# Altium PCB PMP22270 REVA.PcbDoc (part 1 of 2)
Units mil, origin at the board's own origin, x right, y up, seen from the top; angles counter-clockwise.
Board outline 4330.71 x 3937.01 mil, 4 copper layers (Top Layer, Signal Layer 1, Signal Layer 2, Bottom Layer), stack 41.2 mil thick; 92 components, 40 nets, 216 pads, 127 vias.
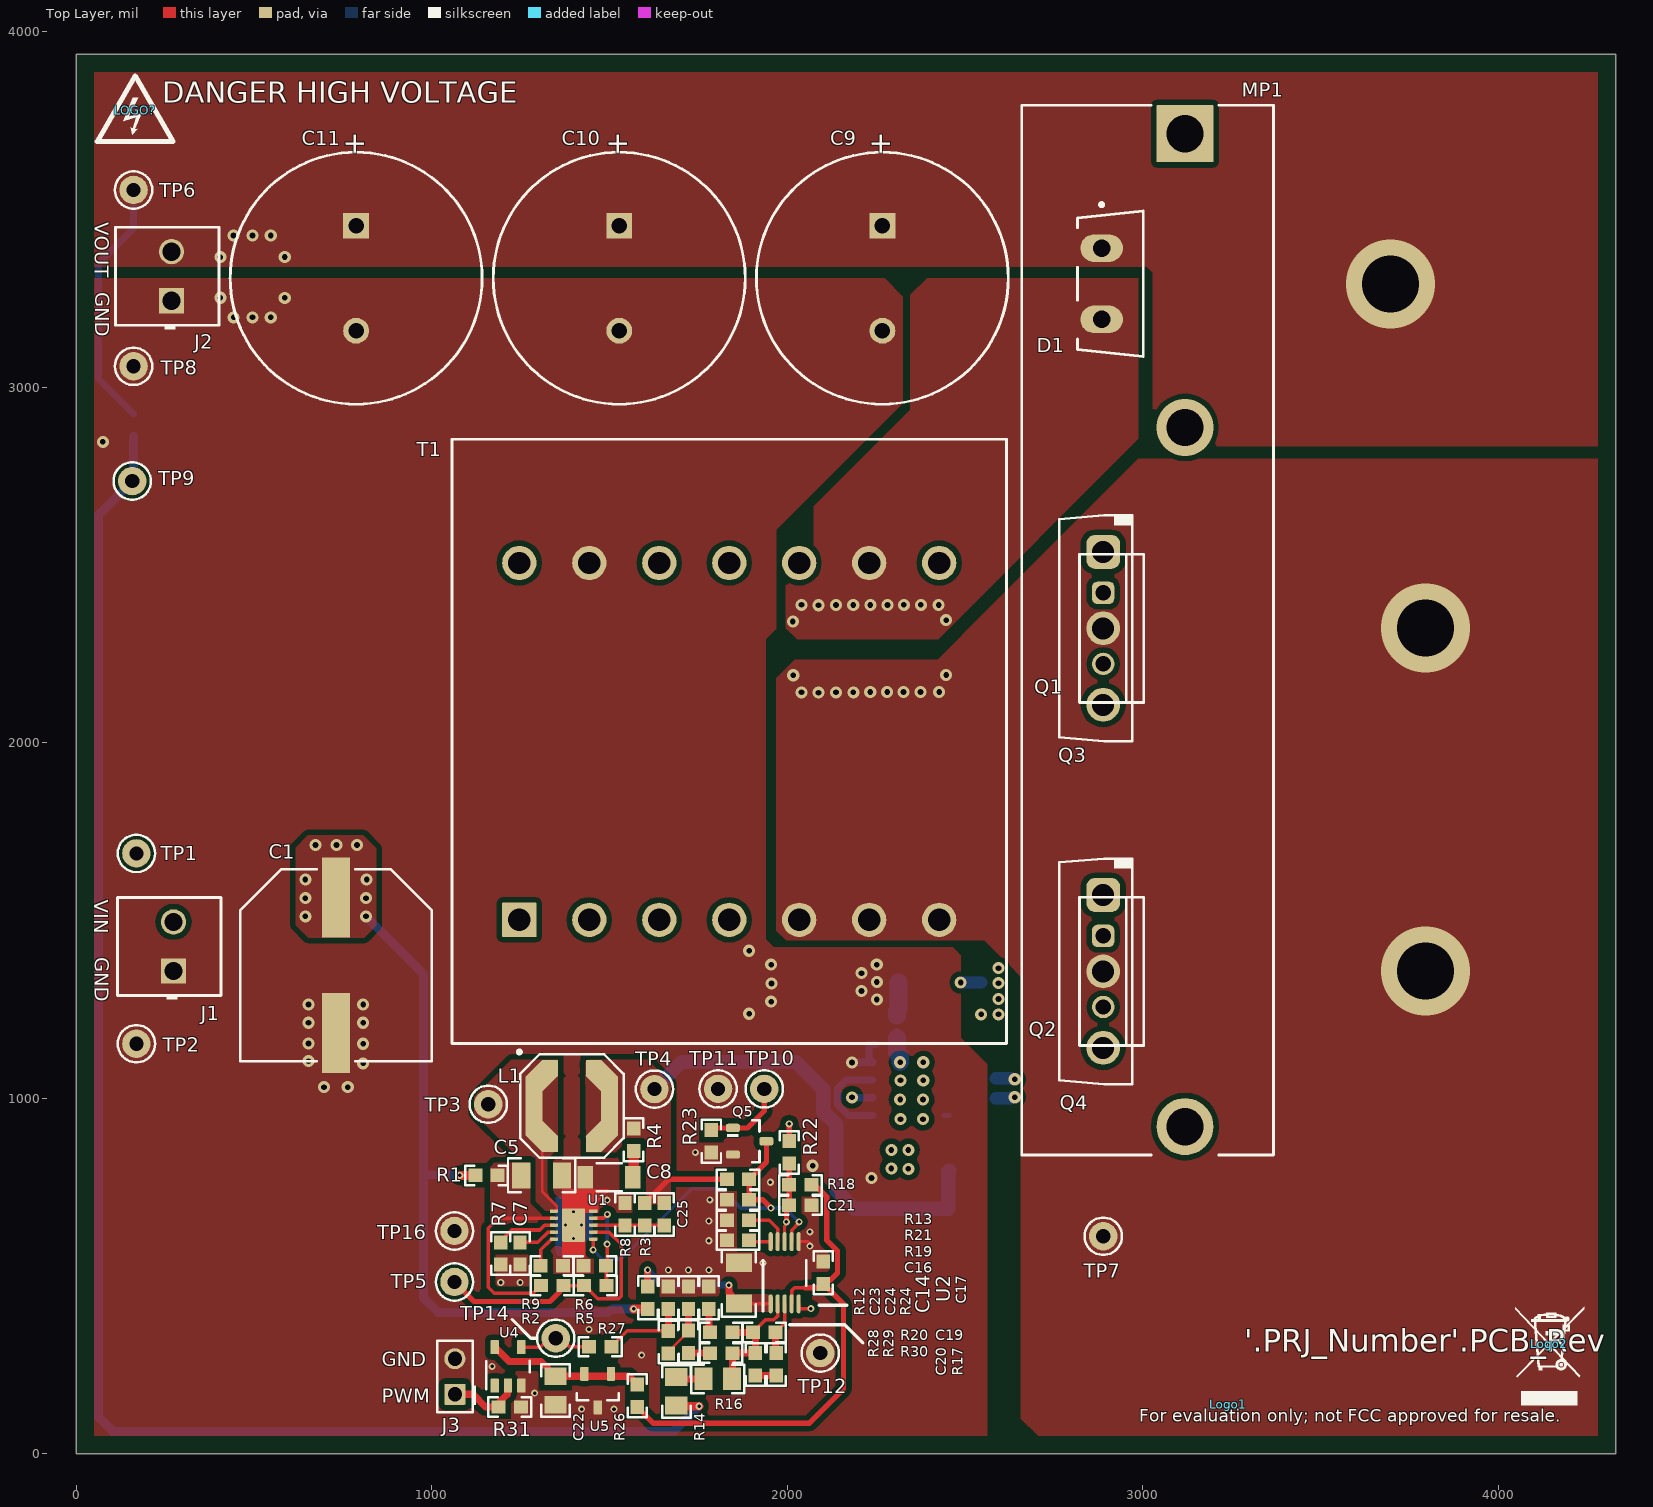
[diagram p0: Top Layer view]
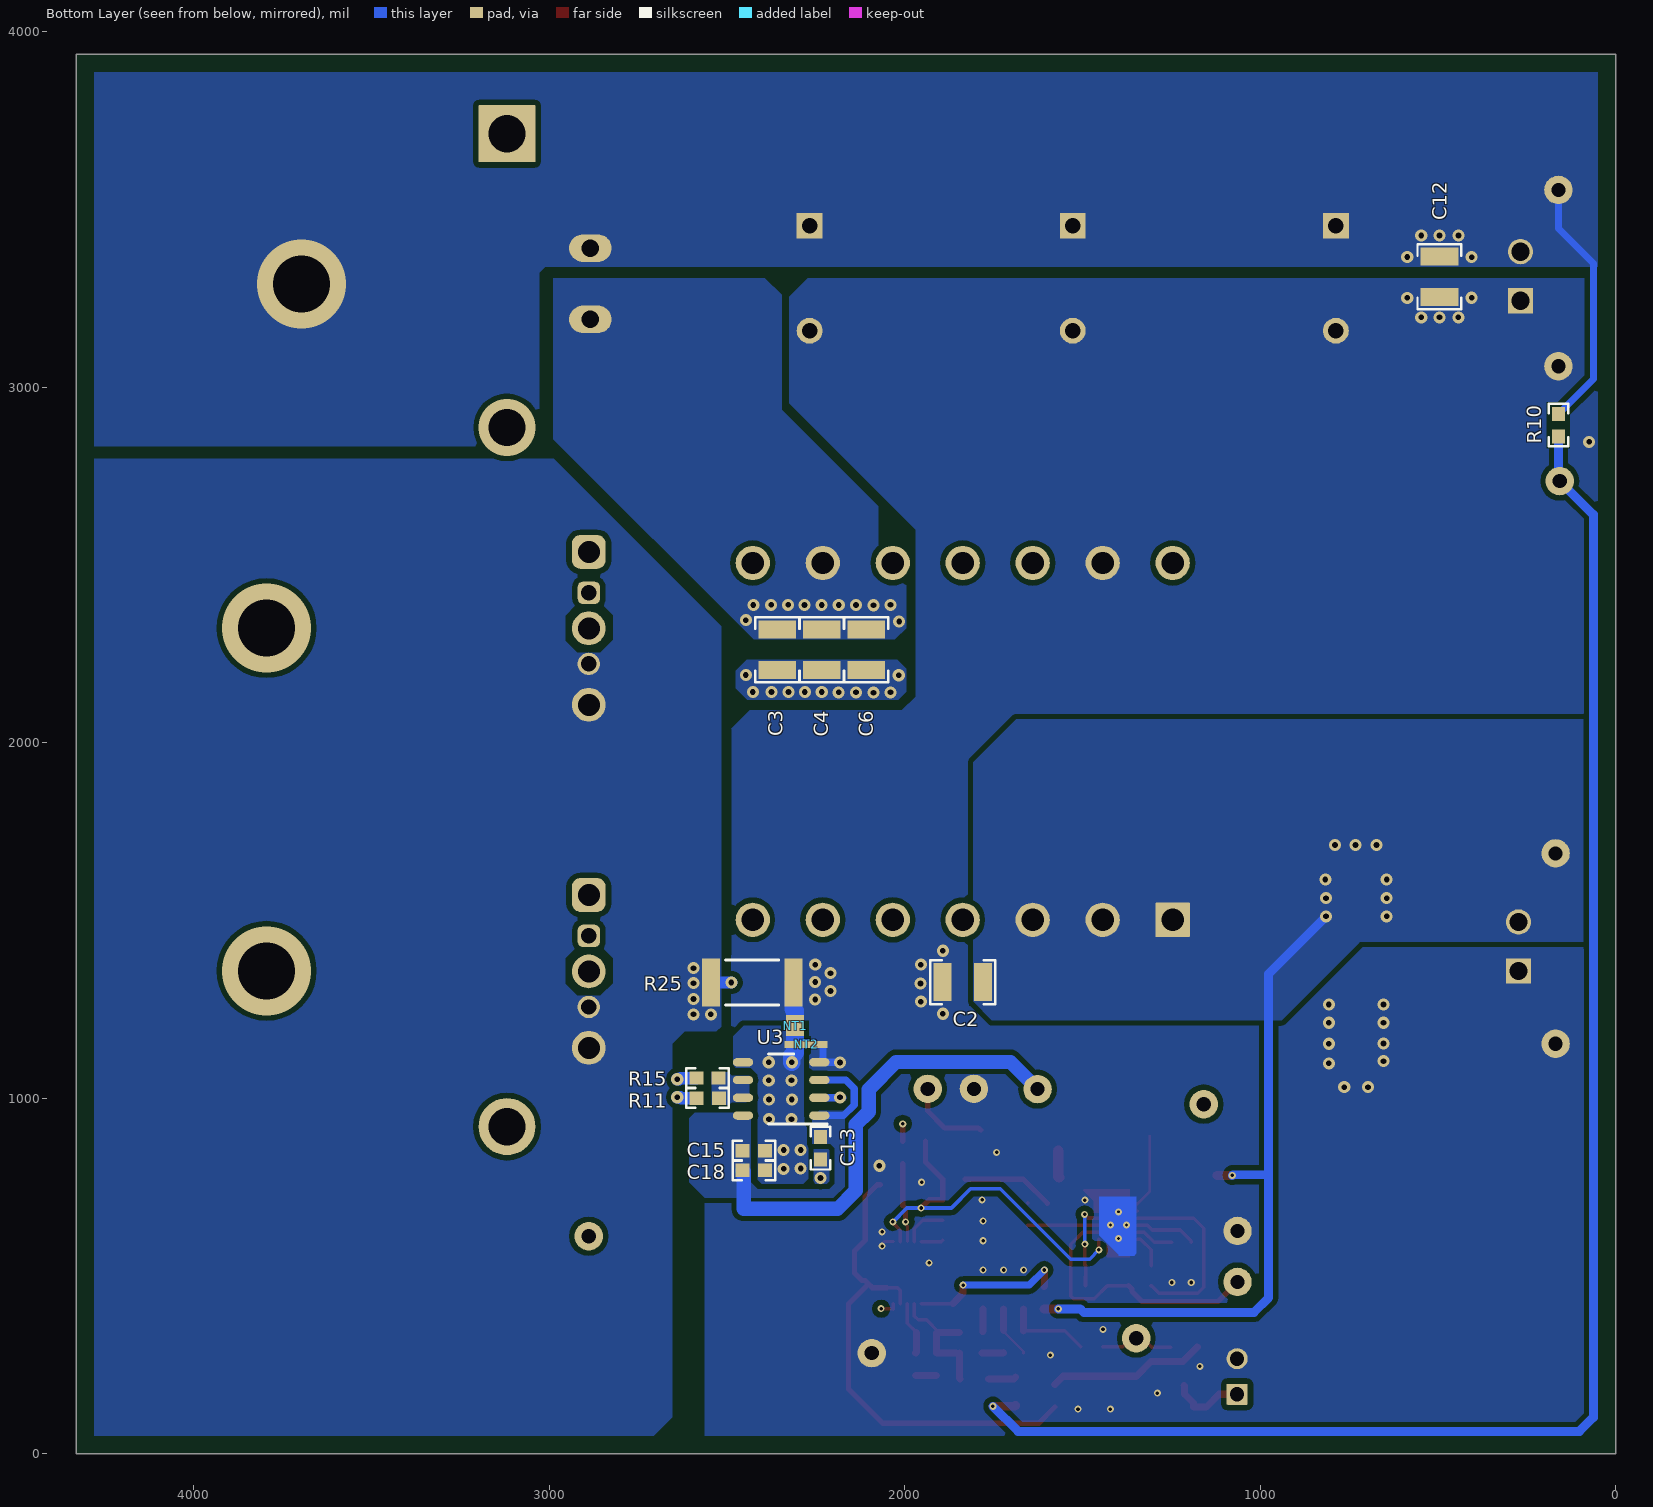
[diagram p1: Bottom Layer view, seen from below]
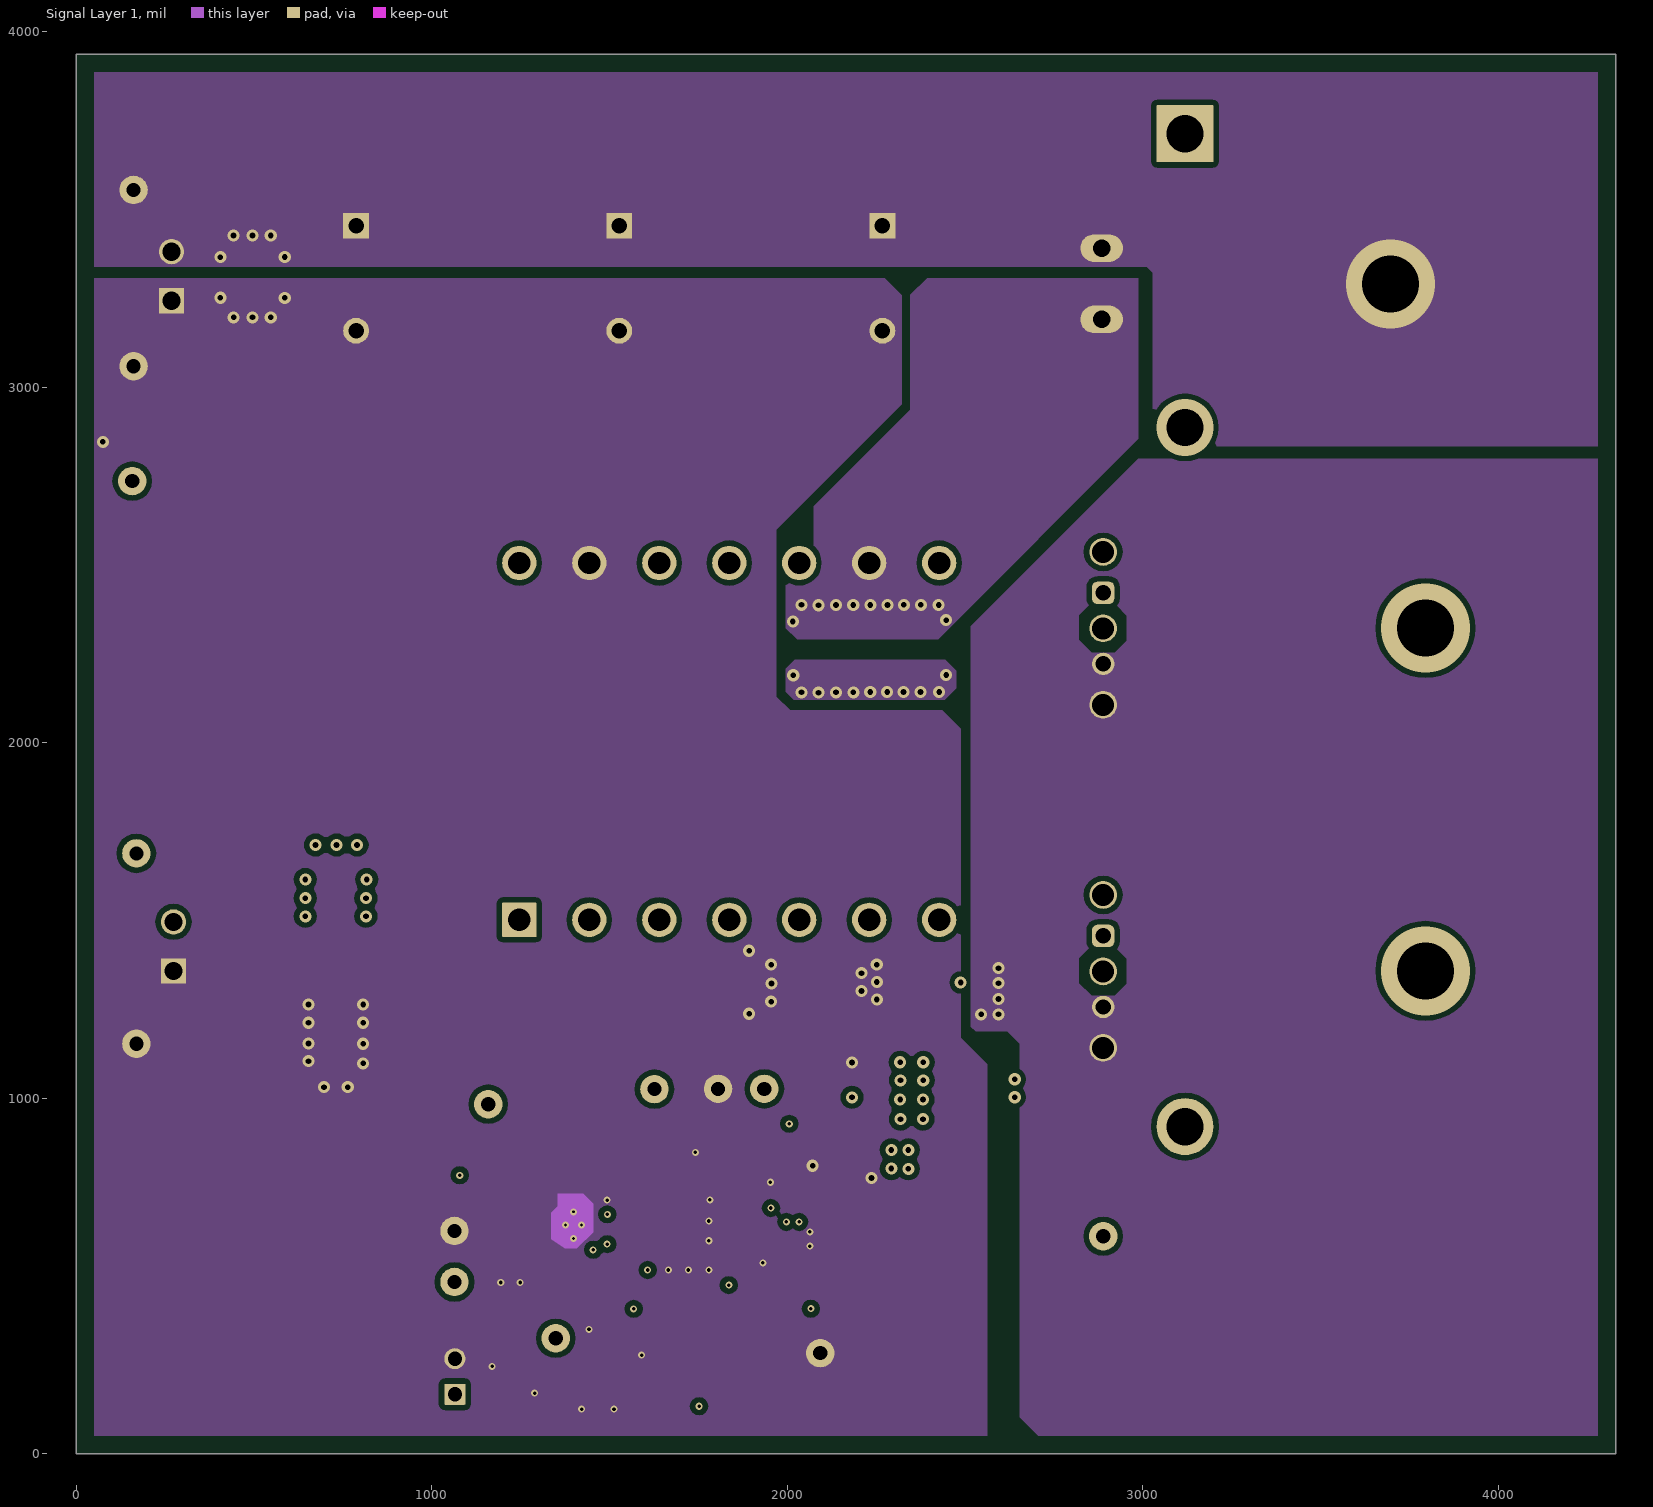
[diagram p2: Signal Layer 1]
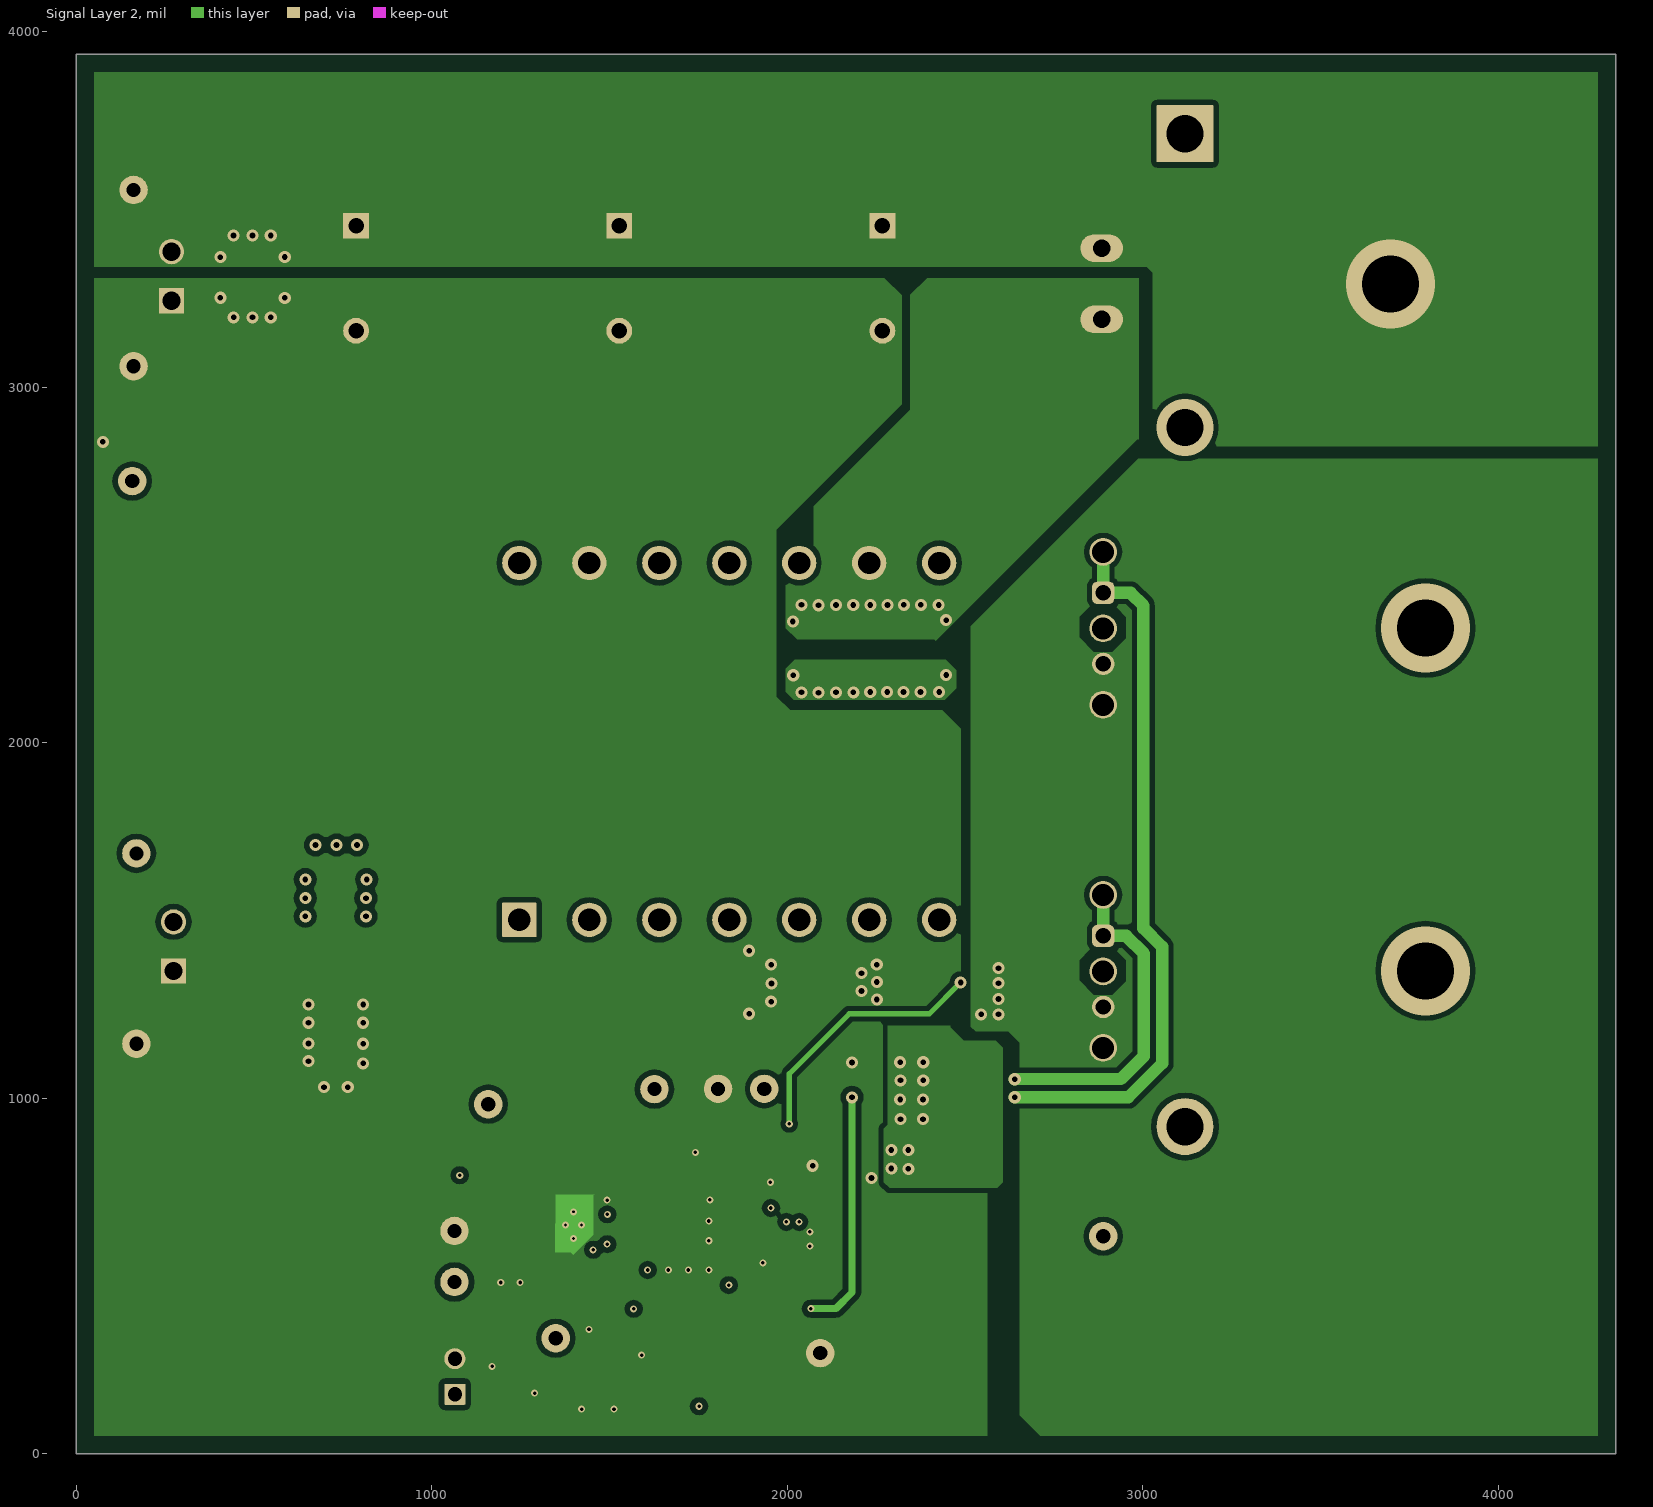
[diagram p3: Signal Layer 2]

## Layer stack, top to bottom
Top Solder: solder mask 0.4, Solder Resist, Dk 3.5
Top Layer: signal copper 2.8
Dielectric1: core 10, FR-4, Dk 4.8
Signal Layer 1: signal copper 2.8
Dielectric 2: core 10, Dk 4.2
Signal Layer 2: signal copper 2.8
Dielectric 3: core 10, Dk 4.2
Bottom Layer: signal copper 2.8
Bottom Solder: solder mask 0.4, Solder Resist, Dk 3.5

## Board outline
0,0 4330.71,0 4330.71,3937.01 0,3937.01

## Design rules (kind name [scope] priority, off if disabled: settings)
AcuteAngle [All] p1: minimum=4.50000000000000E+0001 checktracksonly=FALSE
AssemblyTestPointUsage [All] p1: valid=2
BoardOutlineClearance BoardOutlineClearance_MountingHoles [OnCopper and InComponentClass('Mounting Holes')] p1: gap=39.37 ignorepadtopadclearanceinfootprint=FALSE
BoardOutlineClearance BoardOutlineClearance_Poly [OnCopper and IsPoly] p2: gap=50 ignorepadtopadclearanceinfootprint=FALSE
BoardOutlineClearance [OnCopper and Not InComponentClass('Logo') and not InComponentClass('FiducialMark') and not InRegion(1000,500,4000,800) and not InPoly] p3: gap=50 ignorepadtopadclearanceinfootprint=FALSE
Clearance Clearance_Keepouts [((IsTrack Or IsArc) And Not InPoly) And IsFree and IsKeepOut vs ((IsTrack Or IsArc) And Not InPoly) And IsFree and IsKeepOut] p1: gap=0 ignorepadtopadclearanceinfootprint=FALSE
Clearance Clearance_Poly [InPolygon] p2: gap=15 ignorepadtopadclearanceinfootprint=TRUE
Clearance Clearance_FiducialMark [IsKeepOut and InComponentClass('FiducialMark') vs IsPad and InComponentClass('FiducialMark')] p3: gap=0 ignorepadtopadclearanceinfootprint=FALSE
Clearance [All] p4: gap=8 ignorepadtopadclearanceinfootprint=TRUE
ComponentClearance ComponentClearance_MountingHoles_FiducialMarks [InComponentClass('Mounting Holes') vs InComponentClass('FiducialMark')] p1: gap=50 collisioncheckmode=3 verticalgap=10 showdistances=FALSE
ComponentClearance ComponentClearance_Shunt [InComponentClass('Header') vs InComponentClass('Shunt')] p2: gap=0 collisioncheckmode=3 verticalgap=0 showdistances=FALSE
ComponentClearance ComponentClearance_Logo [InComponentClass('Logo')] p3: gap=50 collisioncheckmode=3 verticalgap=10 showdistances=FALSE
ComponentClearance ComponentClearance_ScrewToNut [(HasFootprint('NY PMS 440 0025 PH')) vs (HasFootprint('Keystone_1902C'))] p4: gap=5 collisioncheckmode=3 verticalgap=10 showdistances=FALSE
ComponentClearance ComponentClearance_MountingHoles [InComponentClass('Mounting Holes')] p5: gap=250 collisioncheckmode=3 verticalgap=100000 showdistances=FALSE
ComponentClearance ComponentClearance_SmallPassives [HasFootprint('0201*') or HasFootprint('0402*') or HasFootprint('0508') or HasFootprint('0603*') or HasFootprint('0612') or HasFootprint('0805*') or HasFootprint('0815*') or HasFootprint('0830*') or HasFootprint('1206*') or HasFootprint('1210*') or HasFootprint('1808*') or HasFootprint('1812*') or HasFootprint('1825*') or HasFootprint('2010*') or HasFootprint('2220*') or HasFootprint('2225*') or HasFootprint('2512*') or HasFootprint('2728*') or HasFootprint('3518*') vs HasFootprint('0201*') or HasFootprint('0402*') or HasFootprint('0508') or HasFootprint('0603*') or HasFootprint('0612') or HasFootprint('0805*') or HasFootprint('0815*') or HasFootprint('0830*') or HasFootprint('1206*') or HasFootprint('1210*') or HasFootprint('1808*') or HasFootprint('1812*') or HasFootprint('1825*') or HasFootprint('2010*') or HasFootprint('2220*') or HasFootprint('2225*') or HasFootprint('2512*') or HasFootprint('2728*') or HasFootprint('3518*')] p6: gap=14.96 collisioncheckmode=3 verticalgap=10 showdistances=FALSE
ComponentClearance ComponentClearance_THtoSMT [IsThruComponent vs IsSMTComponent] p7: gap=40 collisioncheckmode=3 verticalgap=30 showdistances=FALSE
ComponentClearance ComponentClearance_THtoTH [IsThruComponent vs IsThruComponent] p8: gap=30 collisioncheckmode=3 verticalgap=30 showdistances=FALSE
ComponentClearance [All] p9: gap=10 collisioncheckmode=3 verticalgap=10 showdistances=FALSE
DiffPairsRouting [All] p1: maxlimit=100 minlimit=10 mostfreqgap=10 toplayer_minwidth=15 toplayer_maxwidth=15 toplayer_prefwidth=15 midlayer1_minwidth=15 midlayer1_maxwidth=15 midlayer1_prefwidth=15 midlayer2_minwidth=15 midlayer2_maxwidth=15 midlayer2_prefwidth=15 bottomlayer_minwidth=15 bottomlayer_maxwidth=15 bottomlayer_prefwidth=15 maxuncoupledlength=1000
FabricationTestPointUsage TestPointUsage [All] p1: valid=2 allowmultiple=FALSE
FabricationTestpoint Testpoint [All] p1: side=3 testpointundercomponent=TRUE minsize=40 maxsize=100 preferedsize=60 minholesize=0 maxholesize=40 preferedholesize=32 testpointgrid=1 allowsidetop=TRUE allowsidebottom=TRUE usegrid=TRUE gridtolerance=0.01
FanoutControl Fanout_LCC [IsLCC] p1: bgadir=Out bgaviamode=Centered fanoutstyle=Auto fanoutdirection=Alternating viagrid=1 // Fanout_LCC (Default Rule)
FanoutControl Fanout_BGA [IsBGA] p2: bgadir=Out bgaviamode=Centered fanoutstyle=Auto fanoutdirection=Alternating viagrid=1 // Fanout_BGA (Default Rule)
FanoutControl Fanout_Default [All] p4: bgadir=Out bgaviamode=Centered fanoutstyle=Auto fanoutdirection=Alternating viagrid=1 // Fanout_Default (Default Rule)
FanoutControl Fanout_Small [(CompPinCount < 5)] p5: bgadir=Out bgaviamode=Centered fanoutstyle=Auto fanoutdirection=OutThenIn viagrid=1 // Fanout_Small (Default Rule)
Height [All] p1: minheight=0 maxheight=4000 prefheight=500
HoleSize [All] p1: absolutevalues=TRUE maxlimit=251 minlimit=7.87 maxpercent=80.000 minpercent=20.000
MinimumAnnularRing MinimumAnnularRing_ThermalPadVias [IsVia and InAnyComponent] p1: minimumring=5.91
MinimumAnnularRing [All] p2: minimumring=4
MinimumSolderMaskSliver MinimumSolderMaskSliver_PadPad [IsPad vs IsPad] p1: minsoldermaskwidth=0.1
MinimumSolderMaskSliver MinimumSolderMaskSliver_Via [IsVia] p2: minsoldermaskwidth=0.1
MinimumSolderMaskSliver MinimumSolderMaskSliver_Logo [InComponentClass('Logo') vs InComponentClass('Logo')] p3: minsoldermaskwidth=0.1
MinimumSolderMaskSliver [All] p4: minsoldermaskwidth=0.1
PlaneClearance [All] p1: clearance=10
PlaneConnect [All] p1: planeconnectstyle=Direct reliefexpansion=10 reliefentries=4 reliefconductorwidth=10 reliefairgap=10
PolygonConnect [All] p1: connectstyle=Direct reliefconductorwidth=10 reliefentries=4 polygonreliefangle="90 Angle" airgapwidth=10
RoutingVias ThermalPadVias [IsVia and InAnyComponent] p1: holewidth=7.87 width=19.68 viastyle="Through Hole" minholewidth=7.87 minwidth=19.68 maxholewidth=12.99 maxwidth=23.62
RoutingVias [All] p2: holewidth=10 width=18 viastyle="Through Hole" minholewidth=10 minwidth=18 maxholewidth=40 maxwidth=65
SMDEntry [All] p1 off: side=TRUE corner=TRUE anyangle=FALSE
SMDToCorner [All] p1 off: distance=50000
SilkToBoardRegionClearance [Not ((IsComment or IsDesignator) And (Hide <> 'False')) and not InRegion(1000,500,4000,800)] p1:
SilkToSilkClearance SilkToSilkClearance_Pb-FreeLogo [(HasFootprint('Pb-Free_Overlay_Medium') OR HasFootprint('Pb-Free_Overlay_Small')) vs (HasFootprint('Pb-Free_Overlay_Medium') OR HasFootprint('Pb-Free_Overlay_Small'))] p1: silktosilkclearance=0
SilkToSilkClearance [All] p2: silktosilkclearance=0
SilkToSolderMaskClearance SilkToComponentPadClearance [(IsPad or IsFill or IsRegion) and InAnycomponent] p1: minsilkscreentomaskgap=0 clearancetoexposedcopper=TRUE
SilkToSolderMaskClearance "Silk to Solder Mask Opening" [All] p2: minsilkscreentomaskgap=0 clearancetoexposedcopper=FALSE
SolderMaskExpansion [All] p1: expansion=4
UnRoutedNet [All] p1: checkbadconnections=TRUE
Width [All] p1: maxlimit=100 minlimit=5 preferedwidth=10 checkconnectedcopper=TRUE
12 further rules are at their usual default settings.

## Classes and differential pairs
component class Header: J3

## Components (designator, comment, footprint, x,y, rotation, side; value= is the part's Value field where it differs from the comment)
C1 "EEV-FK1J221Q" SM_RADIAL_H13 730.78,1374.32 r270 top value=220uF
C2 "C3225X7R2A225K230AB" 1210_250 1836.78,1327 r0 bottom value=2.2uF
C3 "GCM32ER71H475KA55L" 1210_270 2358.52,2262 r270 bottom value=4.7uF
C4 "GCM32ER71H475KA55L" 1210_270 2233.52,2262 r270 bottom value=4.7uF
C5 "Capacitor" 1206 1309.09,783.42 r0 top value=1uF
C6 "GCM32ER71H475KA55L" 1210_270 2108.52,2262 r270 bottom value=4.7uF
C7 "GRM188R71C473KA01D" 0603 1248.49,563.42 r270 top value=0.047uF
C8 "GRM31CR71E106KA12L" 1206_180 1499.09,778.42 r180 top value=10uF
C9 "EEUED2E151" CAPPR7.5-18x31.5 2267.72,3306.72 r270 top value=150uF
C10 "EEUED2E151" CAPPR7.5-18x31.5 1527.56,3306.72 r270 top value=150uF
C11 "EEUED2E151" CAPPR7.5-18x31.5 787.4,3306.72 r270 top value=150uF
C12 "GRM32DR72E104KW01L" 1210_220 496.06,3311.02 r270 bottom value=0.1uF
C13 "C0603C104K5RACAUTO" 0603 2237.22,859.79 r270 bottom value=0.1uF
C14 "Capacitor" 1206 1864.08,480.24 r90 top value=1uF
C15 "C0603C104K5RACAUTO" 0603 2424.46,852.93 r180 bottom value=0.1uF
C16 "Capacitor" 0603 1861.56,600.97 r180 top value=0.47uF
C17 "Capacitor" 0603 2101.56,509.31 r90 top value=1uF
C18 "Capacitor" 0603 2424.46,797.32 r180 bottom value=1uF
C19 "CGA3E2NP01H101J080AA" 0603 1935.57,341.72 r180 top value=100pF
C20 "C0603C104K5RACAUTO" 0603 1910.34,251.72 r90 top value=0.1uF
C21 "GRM1885C1H221JA01D" 0603 2037.19,699.31 r0 top value=220pF
C22 "GCM21BC71C106KE36L" 0805_HV 1348.09,178.33 r270 top value=10uF
C23 "CGA3E3X7R1H154K080AB" 0603 1665.59,439.1 r90 top value=0.15uF
C24 "CGA3E3X7R1H154K080AB" 0603 1722.07,439.1 r90 top value=0.15uF
C25 "C1608C0G1H100D080AA" 0603 1654.09,673.42 r270 top value=10pF
D1 "C6D10065A" FP-C6D10065A_TO220-2-MFG 2908.72,3291.34 r0 top
J1 "691214110002" Wurth_691214110002 273.64,1427.34 r90 top
J2 "691214110002" Wurth_691214110002 268.14,3312.63 r90 top
J3 "Header_2x1" CONN_PEC02SAAN 1065.16,217.54 r90 top
L1 "Inductor_Iron" LPS6235 1394.16,978.42 r0 top value=470uH
Logo1 "FCC disclaimer" FCC_disclaimer 3240,140 r0 top
Logo2 "WEEE logo" WEEE_Minimum 4143,309 r0 top
LOGO? "DANGER HIGH VOLTAGE" IEC_HighVoltage_Small 166,3779 r0 top
MP1 "OMNI-220-18-75-3C" FP-OMNI-220-18-75-3C_PTH_HTSNK_75MM0_18MM0-MFG 3013.83,2317 r270 top
NT1 "Net-Tie" Net-Tie_50milWide_30milLong 2308.55,1204.79 r270 bottom net-tie
NT2 "Net-Tie" Net-Tie_20milWide_60milLong 2277.77,1151.47 r0 bottom net-tie
Q1 "IPP410N30NAKSA1" TO-220-3 2888.83,2322 r270 top value=300V
Q2 "IPP410N30NAKSA1" TO-220-3 2888.83,1357 r270 top value=300V
Q3 "IPW65R019C7FKSA1" TO-247 2888.83,2322 r270 top value=700V
Q4 "IPW65R019C7FKSA1" TO-247 2888.83,1357 r270 top value=700V
Q5 "2N7002P,215" SOT-23 1894.31,879.31 r0 top value=60V
R1 "CRCW06030000Z0EA" 0603 1154.09,783.42 r180 top value=0
R2 "CRCW0603499KFKEA" 0603 1339.09,473.42 r180 top value=499k
R3 "CRCW060371K5FKEA" 0603 1599.09,673.42 r90 top value=71.5k
R4 "CRCW06033R32FKEA" 0603 1567.98,883.42 r90 top value=3.32
R5 "CRCW060316K9FKEA" 0603 1460.11,473.42 r180 top value=16.9k
R6 "CRCW06030000Z0EA" 0603 1459.09,528.98 r0 top value=0
R7 "CRCW06030000Z0EA" 0603 1194.09,563.42 r90 top value=0
R8 "Resistor" 0603 1543.98,673.42 r270 top value=10.0k
R9 "CRCW0603210KFKEA" 0603 1338.06,528.98 r180 top value=210k
R10 "Resistor" 0603 161.42,2893.7 r270 bottom value=49.9
R11 "CRCW06030000Z0EA" 0603 2554.78,1000.52 r0 bottom value=0
R12 "Resistor" 0603 1608.09,439.1 r270 top value=3.3
R13 "CRCW060310K0FKEA" 0603 1861.56,772.17 r180 top value=10.0k
R14 "CRCW0805499KFKEA" 0805_HV 1688.09,175.77 r270 top value=499k
R15 "CRCW06030000Z0EA" 0603 2555,1057.06 r0 bottom value=0
R16 "CRCW0805499KFKEA" 0805_HV 1804.74,210.77 r180 top value=499k
R17 "CRCW0603100KFKEA" 0603 1969.08,251.72 r90 top value=100k
R18 "CRCW060331K6FKEA" 0603 2037.19,756.56 r0 top value=31.6k
R19 "CRCW060368K1FKEA" 0603 1861.56,656.83 r0 top value=68.1k
R20 "CRCW0603221RFKEA" 0603 1814.08,341.72 r0 top value=221
R21 "CRCW060310K0FKEA" 0603 1861.56,714.31 r0 top value=10.0k
R22 "Resistor" 0603 2005.69,847.82 r90 top value=1.00k
R23 "CRCW060310K0FKEA" 0603 1786.56,879.31 r90 top value=10.0k
R24 "CRCW060312K1FKEA" 0603 1779.63,439.1 r270 top value=12.1k
R25 "CSRN2512FK15L0" 2512 2429.22,1325.79 r0 bottom value=0.015
R26 "CRCW06032K00FKEA" 0603 1578.09,163.41 r90 top value=2.00k
R27 "CRCW06031K00FKEA" 0603 1473.96,301.08 r180 top value=1.00k
R28 "CRCW06031K00FKEA" 0603 1665.59,314.28 r90 top value=1.00k
R29 "CRCW060310K7FKEA" 0603 1722.07,315.77 r270 top value=10.7k
R30 "CRCW060395R3FKEA" 0603 1814.08,283.21 r180 top value=95.3
R31 "CRCW0603100KFKEA" 0603 1219.67,131.95 r180 top value=100k
T1 "750318760" FP-750318760_TRANSFORMER_PTH_14-MFG 1836.98,2003.97 r90 top
TP1 "5000" Keystone5000 169.29,1688.98 r90 top
TP2 "5001" Keystone5001 169.29,1153.54 r90 top
TP3 "5000" Keystone5000 1159.09,983.42 r90 top
TP4 "5000" Keystone5000 1626.53,1025.87 r90 top
TP5 "5000" Keystone5000 1064.09,483.46 r90 top
TP6 "5000" Keystone5000 161.42,3555.12 r90 top
TP7 "5000" Keystone5000 2889,612 r180 top
TP8 "5001" Keystone5001 161.42,3059.06 r90 top
TP9 "5003" Keystone5003 157.48,2736.22 r180 top
TP10 "5000" Keystone5000 1935.51,1026.6 r270 top
TP11 "5001" Keystone5001 1805.51,1026.6 r270 top
TP12 "5001" Keystone5001 2093.09,283.29 r0 top
TP14 "5003" Keystone5003 1348.96,325.14 r270 top
TP16 "5001" Keystone5001 1064.09,627 r90 top
U1 "LM5165DRCR" DRC0010J 1399.09,643.42 r0 top
U2 "LM5022" DGS0010A_N 1992.78,509.32 r90 top
U3 "UCC27322QDRQ1" D0008A_N 2347.77,1026.47 r0 bottom
U4 "SN74LV1T04DBVR" DBV0005A_N 1214.68,246.08 r90 top
U5 "TL432BQDBZRQ1" DBZ0003A_N 1466.95,178.01 r270 top

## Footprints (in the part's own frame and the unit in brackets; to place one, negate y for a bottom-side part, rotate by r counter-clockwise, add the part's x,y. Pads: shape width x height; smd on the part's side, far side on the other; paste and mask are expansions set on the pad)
0603 [mm] "0603 from SM-752 data"
  rect 1x0.95 smd: 1(-0.8,0) 2(0.8,0)
  silkscreen extent -1.52,-0.69 1.52,0.69, body extent -0.87,-0.47 0.87,0.47, height 1
0805_HV [mil] "0805 with 30mil clearance between pads"
  rect 50x63 smd: 1(-40,0) 2(40,0)
  silkscreen extent -74,-40 74,40, body extent -43,-29 43,29, height 57
1206 [mm] "1206 from SM-752 data"
  rect 1.3x1.85 smd: 1(-1.45,0) 2(1.45,0)
  silkscreen extent -2.4,-1.21 2.4,1.21, body extent -1.7,-0.9 1.7,0.9, height 1.35
1206_180 [mm] "1206_180"
  rect 1.1x1.6 smd: 1(-1.7,0) 2(1.7,0)
  silkscreen extent -0.9,-1 0.9,1, body extent -1.75,-0.95 1.75,0.95, height 1.8
1210_220 [mm] "1210"
  rect 1.3x2.7 smd: 1(-1.45,0) 2(1.45,0)
  silkscreen extent -2.32,-1.57 2.32,1.57, body extent -1.7,-1.35 1.7,1.35, height 2.2
1210_250 [mm] "1210"
  rect 1.3x2.7 smd: 1(-1.45,0) 2(1.45,0)
  silkscreen extent -2.32,-1.57 2.32,1.57, body extent -1.7,-1.35 1.7,1.35, height 2.5
1210_270 [mm] "1210"
  rect 1.3x2.7 smd: 1(-1.45,0) 2(1.45,0)
  silkscreen extent -2.32,-1.57 2.32,1.57, body extent -1.7,-1.35 1.7,1.35, height 2.7
2512 [mm] "Chip Resistor, Body 6.3x3.2mm, IPC Medium Density"
  rect 1.3x3.4 smd: 1(-2.95,0) 2(2.95,0)
  silkscreen extent -1.9,-1.6 1.9,1.6, body extent -3.22,-1.67 3.22,1.67, height 0.71
CAPPR7.5-18x31.5 [mm] "Capacitor, Electrolytic, Radial; Body 18 x 31.5 mm (Dia.xH typ); Pin Spacing 7.5 mm (typ)"
  rect 1.85x1.85 hole 1.1: 1(-3.75,0)
  round 1.85 hole 1.1: 2(3.75,0)
  silkscreen extent -9,-9 9,9, body extent -9,-9.01 9,9.01, height 33.5
CONN_PEC02SAAN [mm] "SULLINS"
  rrect7% 1.5x1.5 hole 1.016: 1(-1.27,0)
  round 1.5 hole 1.016: 2(1.27,0)
  silkscreen extent -2.54,-1.52 2.54,1.27, body extent -2.54,-1.27 2.54,1.27, height 8.38
D0008A_N [mm] "SOIC, 8-Leads, Body 4.9x3.9mm, Pitch 1.27mm, IPC Medium Density"
  oval 1.45x0.6 smd: 1(-2.725,1.905) 2(-2.725,0.635) 3(-2.725,-0.635) 4(-2.725,-1.905) 5(2.725,-1.905) 6(2.725,-0.635) 7(2.725,0.635) 8(2.725,1.905)
  silkscreen extent -3.3,-2.5 0.9,2.5, body extent -3,-2.45 3,2.45, height 1.63
DBV0005A_N [mm] "SOT23, 5-Leads, Body 2.9x1.6mm, Pitch 0.95mm, Lead Span 2.8mm, IPC Medium Density"
  rrect17% 1x0.6 smd: 1(-1.375,0.95) 2(-1.375,0) 3(-1.375,-0.95) 4(1.375,-0.95) 5(1.375,0.95)
  silkscreen extent -1.63,-1.55 0.38,1.55, body extent -1.42,-1.46 1.42,1.46, height 1.09
DBZ0003A_N [mm] "SOT23, 3-Leads, Body 2.9x1.3mm, Pitch 0.95mm, Lead Span 2.4mm, IPC Medium Density"
  rrect17% 1x0.6 smd: 1(-1.2,0.95) 2(-1.2,-0.95) 3(1.2,0)
  silkscreen extent 0.2,-1.5 0.7,1.5, body extent -1.26,-1.46 1.26,1.46, height 0.98
DGS0010A_N [mm] "TSSOP, 10-Leads, Body 3x3mm, Pitch 0.5mm, IPC Medium Density"
  oval 1.35x0.3 smd: 1(-2.225,1) 2(-2.225,0.5) 3(-2.225,0) 4(-2.225,-0.5) 5(-2.225,-1) 6(2.225,-1) 7(2.225,-0.5) 8(2.225,0) 9(2.225,0.5) 10(2.225,1)
  silkscreen extent -2.75,-1.55 0.9,1.55, body extent -2.45,-1.5 2.45,1.5, height 0.96
DRC0010J [mm] "VSON-10"
  rrect42% 0.6x0.24 smd: 1(-1.4,1) 2(-1.4,0.5) 3(-1.4,0) 4(-1.4,-0.5) 5(-1.4,-1) 6(1.4,-1) 7(1.4,-0.5) 8(1.4,0) 9(1.4,0.5) 10(1.4,1)
  rrect12% 1.65x2.4 smd paste-1 mask-2: 11(0,0)
  Top Layer region: -0.375,-1.65 -0.375,-1.2 -0.775,-1.2 -0.794,-1.196 -0.81,-1.185 -0.821,-1.169 -0.825,-1.15 -0.825,-1.15 -0.825,1.15 -0.821,1.169 -0.81,1.185 -0.794,1.196 -0.775,1.2 -0.775,1.2 -0.375,1.2 -0.375,1.65 -0.371,1.669 -0.36,1.685 -0.344,1.696 -0.325,1.7 -0.325,1.7 -0.325,1.7 -0.175,1.7 -0.175,1.7 -0.156,1.696 -0.14,1.685 -0.129,1.669 -0.125,1.65 -0.125,1.65 -0.125,1.2 0.125,1.2 0.125,1.65 0.129,1.669 0.14,1.685 0.156,1.696 0.175,1.7 0.175,1.7 0.175,1.7 0.325,1.7 0.325,1.7 0.344,1.696 0.36,1.685 0.371,1.669 0.375,1.65 0.375,1.65 0.375,1.2 0.775,1.2 0.794,1.196 0.81,1.185 0.821,1.169 0.825,1.15 0.825,1.15 0.825,-1.15 0.821,-1.169 0.81,-1.185 0.794,-1.196 0.775,-1.2 0.775,-1.2 0.375,-1.2 0.375,-1.65 0.371,-1.669 0.36,-1.685 0.344,-1.696 0.325,-1.7 0.325,-1.7 0.175,-1.7 0.156,-1.696 0.14,-1.685 0.129,-1.669 0.125,-1.65 0.125,-1.65 0.125,-1.2 -0.125,-1.2 -0.125,-1.65 -0.129,-1.669 -0.14,-1.685 -0.156,-1.696 -0.175,-1.7 -0.175,-1.7 -0.325,-1.7 -0.344,-1.696 -0.36,-1.685 -0.371,-1.669 -0.375,-1.65
  body extent -1.5,-1.5 1.5,1.5, height 1
FCC_disclaimer [mil]
FP-750318760_TRANSFORMER_PTH_14-MFG [mm]
  rrect4% 2.45x2.45 hole 1.6 paste-1000 mask+0: 1(-12.75,15)
  round 2.45 hole 1.6 paste-1000 mask+0: 2(-12.75,10) 3(-12.75,5) 4(-12.75,0) 5(-12.75,-5) 6(-12.75,-10) 7(-12.75,-15) 8(12.75,-15) 9(12.75,-10) 10(12.75,-5) 11(12.75,0) 12(12.75,5) 13(12.75,10) 14(12.75,15)
  silkscreen extent -22.31,-19.8 21.59,19.8, body extent -21.69,-19.9 21.69,19.9, height 0.25
FP-C6D10065A_TO220-2-MFG [mil]
  rrect100% 120x77.56 hole 50 paste-39370.1 mask+0: 1(-24.26,100) 2(-24.26,-100)
  silkscreen extent -92,-205 92,227, body extent -96,-209 96,209, height 10
FP-OMNI-220-18-75-3C_PTH_HTSNK_75MM0_18MM0-MFG [mm]
  rrect2% 4.07x4.07 hole 2.67 paste-1000 mask+0: 1(-35.47,2.67)
  round 4.07 hole 2.67 paste-1000 mask+0: 2(35.47,2.67)
  silkscreen extent -37.5,-9 37.5,9, body extent -37.6,-9.1 37.6,9.1, height 0.25
IEC_HighVoltage_Small [mil]
  silkscreen extent -107,-88 107,97
Keystone5000 [mil] "For Keystone 500x miniature loop terminals"
  round 80 hole 40: 1(0,0)
  silkscreen extent -52,-52 52,52, body extent -49,-49 49,49, height 182
Keystone5001 [mil] "For Keystone 500x miniature loop terminals"
  round 80 hole 40: 1(0,0)
  silkscreen extent -52,-52 52,52, body extent -49,-49 49,49, height 182
Keystone5003 [mil] "For Keystone 500x miniature loop terminals"
  round 80 hole 40: 1(0,0)
  silkscreen extent -52,-52 52,52, body extent -49,-49 49,49, height 182
LPS6235 [mm] "Coilcraft recommended land pattern.  Document 587-2, rev 10/17/08"
  rect 1.2x4.25 smd: 1(-2.7,0) 2(2.7,0)
  rect 1.68x1.6 smd rot 135: 1(-2.126,-2.151) 2(2.126,2.151)
  rect 1.68x1.6 smd rot 45: 1(-2.126,2.151) 2(2.126,-2.151)
  rect 1.125x1.2 smd: 1(-1.562,-2.7) 1(-1.562,2.7) 2(1.562,-2.7) 2(1.562,2.7)
  silkscreen extent -3.7,-3.7 3.7,3.7, body extent -3.1,-3.1 3.1,3.1, height 3.52
Net-Tie_20milWide_60milLong [mil] "20mil net tie, no solder mask opening, no solder paste"
  rect 60x20 smd paste-10 mask-10: 1(-30,0) 2(30,0)
Net-Tie_50milWide_30milLong [mil] "50mil net tie, no solder mask opening, no solder paste"
  rect 30x50 smd paste-20 mask-20: 1(-15,0) 2(15,0)
SM_RADIAL_H13 [mm] "12.5 x 13.5mm:  Panasonic H13"
  rect 5.7x2 smd: 1(-4.85,0) 2(4.85,0)
  silkscreen extent -6.85,-6.85 6.85,6.85, body extent -6.85,-6.85 6.85,6.85, height 14
SOT-23 [mm] "SOT23, 3-Leads, Body 2.9x1.3mm, Pitch 0.95mm, Lead Span 2.5mm, IPC Medium Density"
  rrect50% 1x0.6 smd: 1(-1.2,0.95) 2(-1.2,-0.95) 3(1.2,0)
  silkscreen extent -1.62,-1.5 0.7,1.5, body extent -1.16,-1.45 1.21,1.45, height 1
TO-220-3 [mm] "TH, 3-Leads, Body 10.2235x4.3815mm, Pitch 2.54mm"
  rrect50% 1.6x1.6 hole 1.1: 1(-2.54,0)
  round 1.6 hole 1.1: 2(0,0) 3(2.54,0)
  silkscreen extent -5.3,-1.7 5.3,2.9, body extent -5.27,-1.7 5.28,2.9, height 22.15
TO-247 [mil] "Standard TO-247"
  rrect50% 95x95 / inner round 78 / far side rrect50% 95x95 hole 62: 1(-215,0)
  round 95 / inner round 78 / far side round 95 hole 62: 2(0,0) 3(215,0)
  silkscreen extent -318,-124 318,81, body extent -318,-124 318,81, height 1007
WEEE_Minimum [mil] "WEEElie bin"
  silkscreen extent -95,-172 99,104
Wurth_691214110002 [mm] "Receptacle, 3.5mm, 2x1, TH"
  rect 1.8x1.8 hole 1.3: 1(-1.75,0)
  round 1.8 hole 1.3: 2(1.75,0)
  silkscreen extent -3.8,-3.4 3.5,4, body extent -3.9,-3.4 3.5,4, height 8.5

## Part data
C1: library part CMP-0011214-2, "CAP, AL, 220 uF, 63 V, +/- 20%, 0.16 ohm, AEC-Q200 Grade 2, SMD", Cap_Case=H13, Manufacturer=Panasonic, Supplier Part Number 1=PCE3484CT-ND, Tolerance_%=20%, Value1="0.16 ohm", Value2=63V, ValueDisplayed=220uF
C2: library part CMP-0009152-2, "CAP, CERM, 2.2 uF, 100 V, +/- 10%, X7R", Cap_Case=1210_250, Manufacturer=TDK, TempCo=X7R, Tolerance_%=10%, Value1="0.00173 ohm", Value2=100V, ValueDisplayed=2.2uF
C3 C4 C6: library part CMP-0750153-1, "CAP, CERM, 4.7 µF, 50 V,+/- 10%, X7R, AEC-Q200 Grade 1, 1210", Cap_Case=1210, Manufacturer=MuRata, TempCo=X7R, Tolerance_%=10%, Value2=50V, ValueDisplayed=4.7µF
C5 C14: library part CMP-0008711-2, "CAP, CERM, 1 uF, 100 V, +/- 20%, X7R, 1206", Cap_Case=1206, Manufacturer=TDK, PartNumber=C3216X7R2A105M160AA, Supplier Part Number 1=445-4468-1-ND, TempCo=X7R, Tolerance_%=20%, Value1=Unknown, Value2=100V, ValueDisplayed=1uF
C7: library part CMP-0007397-4, "CAP, CERM, 0.047 uF, 16 V, +/- 10%, X7R, 0603", Cap_Case=0603, Manufacturer=MuRata, Supplier Part Number 1=490-1529-1-ND, TempCo=X7R, Tolerance_%=10%, Value1=Unknown, Value2=16V, ValueDisplayed=0.047uF
C8: library part CMP-0008965-2, "CAP, CERM, 10 uF, 25 V, +/- 10%, X7R, 1206", Cap_Case=2220, Manufacturer=MuRata, Supplier Part Number 1=81-GRM31CR71E106KA12, TempCo=X7R, Tolerance_%=10%, Value1=Unknown, Value2=25V, ValueDisplayed=10uF
C9 C10 C11: library part CMP-0010013-3, "CAP, AL, 150 uF, 250 V, +/- 20%, TH", AC_Derating=0.35, Manufacturer=Panasonic, Tolerance_%=20%, Value2=250V, ValueDisplayed=150uF
C12: library part CMP-0009192-2, "CAP, CERM, 0.1 uF, 250 V, +/- 10%, X7R, 1210", Cap_Case=1210, Manufacturer=MuRata, Supplier Part Number 1=490-3541-1-ND, TempCo=X7R, Tolerance_%=10%, Value1=Unknown, Value2=250V, ValueDisplayed=0.1uF
C13 C15 C20: library part CMP-0079602-1, "CAP, CERM, 0.1 µF, 50 V,+/- 10%, X7R, AEC-Q200 Grade 1, 0603", Cap_Case=0603, Manufacturer=Kemet, Supplier Part Number 1=399-6856-1-ND, TempCo=X7R, Tolerance_%=10%, Value2=50V, ValueDisplayed=0.1µF
C16: library part CMP-0007050-4, "CAP, CERM, 0.47 uF, 50 V, +/- 10%, X7R, 0603", Cap_Case=0603, Manufacturer=TDK, PartNumber=C1608X7R1H474K080AC, Supplier Part Number 1=445-5952-1-ND, TempCo=X7R, Tolerance_%=10%, Value1="0.010974 ohm", Value2=50V, ValueDisplayed=0.47uF
C17 C18: library part CMP-0007037-4, "CAP, CERM, 1 uF, 16 V, +/- 10%, X7R, 0603", Cap_Case=0603, Manufacturer=TDK, PartNumber=C1608X7R1C105K080AC, Supplier Part Number 1=445-1604-1-ND, TempCo=X7R, Tolerance_%=10%, Value1="0.0057 ohm", Value2=16V, ValueDisplayed=1uF
C19: library part CMP-0007075-4, "CAP, CERM, 100 pF, 50 V, +/- 5%, C0G/NP0, AEC-Q200 Grade 0, 0603", Cap_Case=0603, Manufacturer=TDK, Supplier Part Number 1=445-12386-1-ND, TempCo=C0G/NP0, Tolerance_%=5%, Value1=Unknown, Value2=50V, ValueDisplayed=100pF
C21: library part CMP-0007197-4, "CAP, CERM, 220 pF, 50 V, +/- 5%, C0G/NP0, 0603", Cap_Case=0603, Manufacturer=MuRata, Supplier Part Number 1=490-1435-1-ND, TempCo=C0G/NP0, Tolerance_%=5%, Value1=Unknown, Value2=50V, ValueDisplayed=220pF
C22: library part CMP-0008012-2, "CAP, CERM, 10 uF, 16 V, +/- 10%, X7S, AEC-Q200 Grade 1, 0805", Cap_Case=0805, Manufacturer=MuRata, Supplier Part Number 1=81-GCM21BC71C106KE6L, TempCo=X7S, Tolerance_%=10%, Value1=Unknown, Value2=16V, ValueDisplayed=10uF
C23 C24: library part CMP-0007093-5, "CAP, CERM, 0.15 uF, 50 V, +/- 10%, X7R, AEC-Q200 Grade 1, 0603", Cap_Case=0603, Manufacturer=TDK, Supplier Part Number 1=445-6925-1-ND, TempCo=X7R, Tolerance_%=10%, Value1="0.028863 ohm", Value2=50V, ValueDisplayed=0.15uF
C25: library part CMP-0006988-4, "CAP, CERM, 10 pF, 50 V, +/- 5%, C0G/NP0, 0603", Cap_Case=0603, Manufacturer=TDK, Supplier Part Number 1=445-1269-1-ND, TempCo=C0G/NP0, Tolerance_%=5%, Value1="0.3492 ohm", Value2=50V, ValueDisplayed=10pF
D1: library part CMP-0087641-2, "Diode Silicon Carbide Schottky 650V 37A (DC) Through Hole TO-220-2", Manufacturer=Cree
J1 J2: library part CMP-0054825-2, "Terminal Block, 3.5mm, 2x1, Tin, TH", Color=Green, Current_A=10A, Manufacturer="Wurth Elektronik", Supplier Part Number 1=732-2747-ND, Voltage_V=300V
J3: library part CMP-0002337-1, "Header, 100mil, 2x1, Tin, TH", Color=Black, Current_A=3A, Manufacturer="Sullins Connector Solutions", PartNumber=PEC02SAAN, Supplier Part Number 1=S1012E-02-ND, Voltage_V=1.8kV
L1: library part CMP-0061837-2, "Inductor, Shielded Drum Core, Ferrite, 470 uH, 0.26 A, 1.6 ohm, SMD", Manufacturer=Coilcraft, PartNumber=LPS6235-474MLB, Value1="1.6 ohm", Value2=0.26A, ValueDisplayed=470uH
Logo1: library part CMP-0074847-1, "FCC_disclaimer"
Logo2: library part CMP-0074769-1
LOGO?: library part CMP-0074835-1, "IEC 61010-1 High Voltage Warning"
MP1: library part CMP-0086954-1, "OmniKlip Heat Sink w/3 clips, 18mm wide, 75mm long, black anodized for TO-220", Manufacturer=Wakefield-Vette
NT1 NT2: library part CMP-0078142-3, "Single point connection between nets.", Manufacturer=N/A
Q1 Q2: library part CMP-0085354-1, "MOSFET, N-CH, 300 V, 44 A, TO-220-3", Alternate Manufacturer=None, Manufacturer="Infineon Technologies", Value1="? ohm", Value2="65 nC"
Q3 Q4: library part CMP-0001229-3, "MOSFET, N-CH, 700 V, 0.019 Ohm, TO-247", Alternate Manufacturer=None, Manufacturer="Infineon Technologies", Value2="215 nC"
Q5: library part CMP-0000775-2, "MOSFET, N-CH, 60 V, 0.36 A, SOT-23", Alternate Manufacturer=None, Manufacturer=Nexperia, Supplier Part Number 1=568-5818-1-ND, Value2="0.6 nC"
R1 R6 R7 R11 R15: library part CMP-0025697-4, "RES, 0, 5%, 0.1 W, AEC-Q200 Grade 0, 0603", Manufacturer=Vishay-Dale, Power_W=100mW, Supplier Part Number 1=541-0.0GCT-ND, TempCo="200 ppm/C", Tolerance_%=5%, Value2=0.1W, Value_Code=0000, ValueDisplayed=0
R2: library part CMP-0022445-4, "RES, 499 k, 1%, 0.1 W, AEC-Q200 Grade 0, 0603", Manufacturer=Vishay-Dale, Power_W=100mW, Supplier Part Number 1=541-499KHCT-ND, TempCo="100 ppm/C", Tolerance_%=1%, Value2=0.1W, Value_Code=499k
R3: library part CMP-0022581-4, "RES, 71.5 k, 1%, 0.1 W, AEC-Q200 Grade 0, 0603", Manufacturer=Vishay-Dale, Power_W=100mW, Supplier Part Number 1=541-71.5KHCT-ND, TempCo="100 ppm/C", Tolerance_%=1%, Value2=0.1W, Value_Code=71k5, ValueDisplayed=71.5k
R4: library part CMP-0022400-4, "RES, 3.32, 1%, 0.1 W, AEC-Q200 Grade 0, 0603", Manufacturer=Vishay-Dale, Power_W=100mW, Supplier Part Number 1=541-3.32HHCT-ND, TempCo="100 ppm/C", Tolerance_%=1%, Value2=0.1W, Value_Code=3R32, ValueDisplayed=3.32
R5: library part CMP-0022081-4, "RES, 16.9 k, 1%, 0.1 W, AEC-Q200 Grade 0, 0603", Manufacturer=Vishay-Dale, Power_W=100mW, Supplier Part Number 1=541-16.9KHCT-ND, TempCo="100 ppm/C", Tolerance_%=1%, Value2=0.1W, Value_Code=16k9, ValueDisplayed=16.9k
R8: library part CMP-0021998-4, "RES, 10.0 k, 1%, 0.1 W, AEC-Q200 Grade 0, 0603", Manufacturer=Vishay-Dale, PartNumber=CRCW060310K0FKEA, Power_W=100mW, Supplier Part Number 1=541-10.0KHCT-ND, TempCo="100 ppm/C", Tolerance_%=1%, Value2=0.1W, Value_Code=10k0, ValueDisplayed=10.0k
R9: library part CMP-0022208-4, "RES, 210 k, 1%, 0.1 W, AEC-Q200 Grade 0, 0603", Manufacturer=Vishay-Dale, Power_W=100mW, Supplier Part Number 1=541-210KHCT-ND, TempCo="100 ppm/C", Tolerance_%=1%, Value2=0.1W, Value_Code=210k
R10: library part CMP-0022448-4, "RES, 49.9, 1%, 0.1 W, AEC-Q200 Grade 0, 0603", Manufacturer=Vishay-Dale, PartNumber=CRCW060349R9FKEA, Power_W=100mW, Supplier Part Number 1=541-49.9HCT-ND, TempCo="100 ppm/C", Tolerance_%=1%, Value2=0.1W, Value_Code=49R9, ValueDisplayed=49.9
R12: library part CMP-0025805-4, "RES, 3.3, 5%, 0.1 W, AEC-Q200 Grade 0, 0603", Manufacturer=Vishay-Dale, PartNumber=CRCW06033R30JNEA, Power_W=100mW, Supplier Part Number 1=541-3.3GCT-ND, TempCo="200 ppm/C", Tolerance_%=5%, Value2=0.1W, Value_Code=3R30, ValueDisplayed=3.3
R13 R21 R23: library part CMP-0021998-4, "RES, 10.0 k, 1%, 0.1 W, AEC-Q200 Grade 0, 0603", Manufacturer=Vishay-Dale, Power_W=100mW, Supplier Part Number 1=541-10.0KHCT-ND, TempCo="100 ppm/C", Tolerance_%=1%, Value2=0.1W, Value_Code=10k0, ValueDisplayed=10.0k
R14 R16: library part CMP-0021281-3, "RES, 499 k, 1%, 0.125 W, AEC-Q200 Grade 0, 0805", Manufacturer=Vishay-Dale, Power_W=125mW, Supplier Part Number 1=541-499KCCT-ND, TempCo="100 ppm/C", Tolerance_%=1%, Value2=0.125W, Value_Code=499k
R17 R31: library part CMP-0021990-4, "RES, 100 k, 1%, 0.1 W, AEC-Q200 Grade 0, 0603", Manufacturer=Vishay-Dale, Power_W=100mW, Supplier Part Number 1=541-100KHCT-ND, TempCo="100 ppm/C", Tolerance_%=1%, Value2=0.1W, Value_Code=100k
R18: library part CMP-0022330-4, "RES, 31.6 k, 1%, 0.1 W, AEC-Q200 Grade 0, 0603", Manufacturer=Vishay-Dale, Power_W=100mW, Supplier Part Number 1=541-31.6KHCT-ND, TempCo="100 ppm/C", Tolerance_%=1%, Value2=0.1W, Value_Code=31k6, ValueDisplayed=31.6k
R19: library part CMP-0022552-4, "RES, 68.1 k, 1%, 0.1 W, AEC-Q200 Grade 0, 0603", Manufacturer=Vishay-Dale, Power_W=100mW, Supplier Part Number 1=541-68.1KHCT-ND, TempCo="100 ppm/C", Tolerance_%=1%, Value2=0.1W, Value_Code=68k1, ValueDisplayed=68.1k
R20: library part CMP-0022217-5, "RES, 221, 1%, 0.1 W, AEC-Q200 Grade 0, 0603", Manufacturer=Vishay-Dale, Power_W=100mW, Supplier Part Number 1=541-221HCT-ND, TempCo="100 ppm/C", Tolerance_%=1%, Value2=0.1W, Value_Code=221R, ValueDisplayed=221
R22: library part CMP-0022109-5, "RES, 1.00 k, 1%, 0.1 W, AEC-Q200 Grade 0, 0603", Manufacturer=Vishay-Dale, PartNumber=CRCW06031K00FKEA, Power_W=100mW, Supplier Part Number 1=541-1.00KHCT-ND, TempCo="100 ppm/C", Tolerance_%=1%, Value2=0.1W, Value_Code=1k00, ValueDisplayed=1.00k
R24: library part CMP-0022030-4, "RES, 12.1 k, 1%, 0.1 W, AEC-Q200 Grade 0, 0603", Manufacturer=Vishay-Dale, Power_W=100mW, Supplier Part Number 1=541-12.1KHCT-ND, TempCo="100 ppm/C", Tolerance_%=1%, Value2=0.1W, Value_Code=12k1, ValueDisplayed=12.1k
R25: library part CMP-0015772-2, "RES, 0.015, 1%, 2 W, 2512", Manufacturer="Stackpole Electronics Inc", Power_W=2W, Supplier Part Number 1=CSRN2512FK15L0CT-ND, TempCo="200 ppm/C", Tolerance_%=1%, Value_Code=R015, ValueDisplayed=0.015
R26: library part CMP-0022268-4, "RES, 2.00 k, 1%, 0.1 W, AEC-Q200 Grade 0, 0603", Manufacturer=Vishay-Dale, Power_W=100mW, Supplier Part Number 1=541-2.00KHCT-ND, TempCo="100 ppm/C", Tolerance_%=1%, Value2=0.1W, Value_Code=2k00, ValueDisplayed=2.00k
R27 R28: library part CMP-0022109-5, "RES, 1.00 k, 1%, 0.1 W, AEC-Q200 Grade 0, 0603", Manufacturer=Vishay-Dale, Power_W=100mW, Supplier Part Number 1=541-1.00KHCT-ND, TempCo="100 ppm/C", Tolerance_%=1%, Value2=0.1W, Value_Code=1k00, ValueDisplayed=1.00k
R29: library part CMP-0022001-4, "RES, 10.7 k, 1%, 0.1 W, AEC-Q200 Grade 0, 0603", Manufacturer=Vishay-Dale, Power_W=100mW, Supplier Part Number 1=541-10.7KHCT-ND, TempCo="100 ppm/C", Tolerance_%=1%, Value2=0.1W, Value_Code=10k7, ValueDisplayed=10.7k
R30: library part CMP-0022660-4, "RES, 95.3, 1%, 0.1 W, AEC-Q200 Grade 0, 0603", Manufacturer=Vishay-Dale, Power_W=100mW, Supplier Part Number 1=541-95.3HCT-ND, TempCo="100 ppm/C", Tolerance_%=1%, Value2=0.1W, Value_Code=95R3, ValueDisplayed=95.3
T1: library part CMP-0088074-1, "TRANSFORMER", Manufacturer="Wurth Electronics"
TP1 TP3 TP4 TP5 TP6 TP7 TP10: library part CMP-0055137-1, "Test Point, Miniature, Red, TH", Color=Red, Manufacturer=Keystone, Supplier Part Number 1=36-5000-ND
TP2 TP8 TP11 TP12 TP16: library part CMP-0055138-1, "Test Point, Miniature, Black, TH", Color=Black, Manufacturer=Keystone, Supplier Part Number 1=36-5001-ND
TP9 TP14: library part CMP-0055140-1, "Test Point, Miniature, Orange, TH", Color=Orange, Manufacturer=Keystone, Supplier Part Number 1=36-5003-ND
U1: library part CMP-0076321-6, "3V-65V, 150mA Synchronous Buck Converter With Ultra-Low IQ, DRC0010J (VSON-10)", Alternate Manufacturer="Texas Instruments", Alternate PartNumber=LM5165DRCT, Operating Temperature Range="-40 to 150 C", Rating=Catalog
U2: library part CMP-0076391-1, "2.2MHz 60-V Low Side Controller for Boost, SEPIC and Flyback, DGS0010A (VSSOP-10)", Alternate Manufacturer="Texas Instruments", Alternate PartNumber=LM5022QDGSTQ1, PartNumber=LM5022QDGSRQ1
U3: library part CMP-0073898-1, "Automotive Catalog Single 9-A High Speed Low-Side MOSFET Driver With Enable, D0008A (SOIC-8)", Alternate Manufacturer="Texas Instruments"
U4: library part CMP-0051667-2, "Single Power Supply INVERTER Gate logic level shifter, DBV0005A (SOT-23-5)", F @ Nom Voltage(Max)(Mhz)=50, Generic Part Number=SN74LV1T04, ICC @ Nom Voltage(Max)(mA)=0.01, Manufacturer="Texas Instruments", Operating Temperature Range="-40 to 125 C", Rating=Catalog, tpd @ Nom Voltage(Max)(ns)=13,7.5,5.5,7.0, Voltage(Nom)(V)=1.8,2.5,3.3,5.5
U5: library part CMP-0032978-1, "Automotive Catalog Adjustable Precision Shunt Regulator, 34 ppm / degC, 100 mA, -40 to 125 degC, 3-pin SOT-23 (DBZ), Green (RoHS & no Sb/Br)", Manufacturer="Texas Instruments", Rating=Automotive, Temp Coeff(Typ)(ppm/ degree C)=34

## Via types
v1: diameter 34, hole 16, Top Layer to Bottom Layer, 86 vias
v2: diameter 20, hole 10, Top Layer to Bottom Layer, 33 vias
v3: diameter 19.68, hole 7.87, Top Layer to Bottom Layer, 4 vias
v4: diameter 250, hole 160, Top Layer to Bottom Layer, 3 vias
v5: diameter 160.24, hole 105.12, Top Layer to Bottom Layer, 1 vias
